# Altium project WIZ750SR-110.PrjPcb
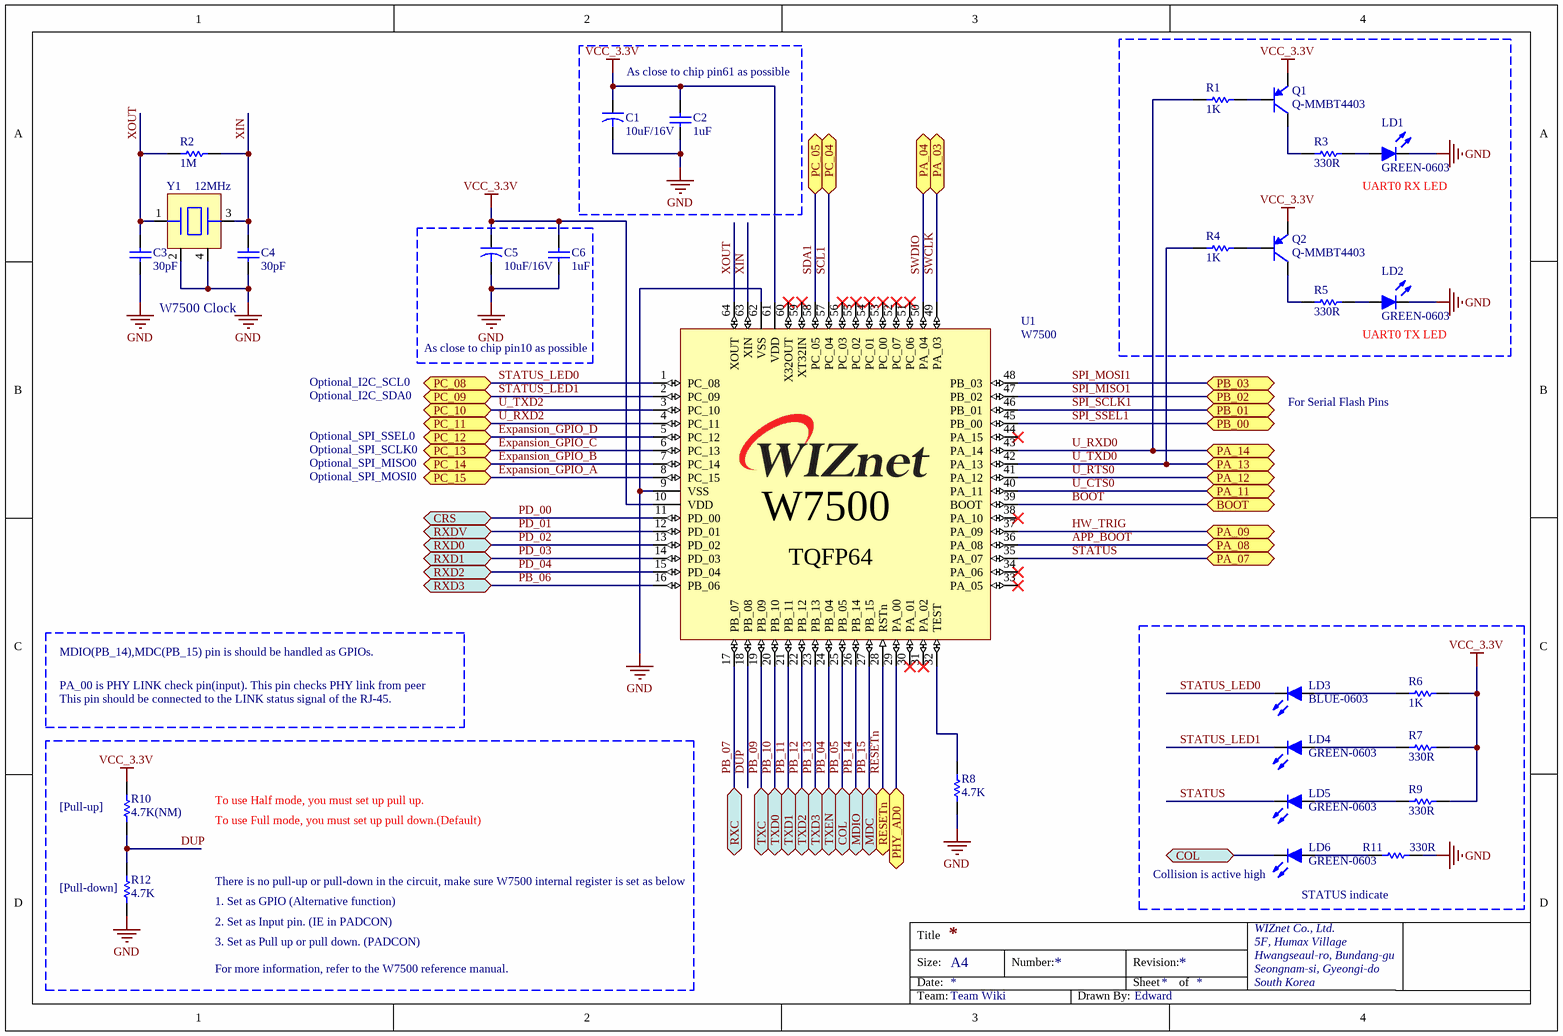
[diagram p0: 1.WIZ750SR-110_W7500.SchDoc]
4 sheets, 94 parts. Net scope: flat (ports and power ports of the same name join across sheets).
Board file: WIZ750SR-110.PcbDoc
Sheets:
  1.WIZ750SR-110_W7500.SchDoc
  2.WIZ750SR-110_IP101GRI.SchDoc
  3.WIZ750SR-110_OPTIONAL.SchDoc
  4.WIZ750SR-110_PINOUT.SchDoc

## Sheet 1.WIZ750SR-110_W7500.SchDoc
size A4; Team: Wiki

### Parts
C1  10uF/16V  [CAP-A Size]
C2  1uF  [CAP-0603]
C3  30pF  [CAP-0603]
C4  30pF  [CAP-0603]
C5  10uF/16V  [CAP-A Size]
C6  1uF  [CAP-0603]
LD1  GREEN-0603  [LED-0603-GREEN]
LD2  GREEN-0603  [LED-0603-GREEN]
LD3  BLUE-0603  [LED-0603-BLUE]
LD4  GREEN-0603  [LED-0603-GREEN]
LD5  GREEN-0603  [LED-0603-GREEN]
LD6  GREEN-0603  [LED-0603-GREEN]
Q1  Q-MMBT4403  [SOT-23-3L]
Q2  Q-MMBT4403  [SOT-23-3L]
R1  1K  [RES-0603]
R2  1M  [RES-0603]
R3  330R  [RES-0603]
R4  1K  [RES-0603]
R5  330R  [RES-0603]
R6  1K  [RES-0603]
R7  330R  [RES-0603]
R8  4.7K  [RES-0603]
R9  330R  [RES-0603]
R10  4.7K(NM)  [RES-0603]
R11  330R  [RES-0603]
R12  4.7K  [RES-0603]
U1  W7500  [W7500-LQFP64]
Y1  12MHz  [OSC-TZ1067B]

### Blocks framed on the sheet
As close to chip pin61 as possible: C1 C2
As close to chip pin10 as possible: C5 C6

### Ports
BOOT, COL, CRS, MDC, MDIO, PA_03, PA_04, PA_07, PA_08, PA_09, PA_11, PA_12, PA_13, PA_14, PB_00, PB_01, PB_02, PB_03, PC_04, PC_05, PC_08, PC_09, PC_10, PC_11, PC_12, PC_13, PC_14, PC_15, PHY_AD0, RESETn, RXC, RXD0, RXD1, RXD2, RXD3, RXDV, TXC, TXD0, TXD1, TXD2, TXD3, TXEN

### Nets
GND: C1.2 C2.1 C3.1 C4.1 C5.2 C6.1 LD1.2(K) LD2.2(K) R8.1 R11.2 R12.1 U1.9(VSS) U1.62(VSS) Y1.2 Y1.4
VCC_3.3V: C1.1 C2.2 C5.1 C6.2 Q1.2(E) Q2.2(E) R6.2 R7.2 R9.2 R10.2 U1.10(VDD) U1.61(VDD)
APP_BOOT: U1.36(PA_08) ; port PA_08
BOOT: U1.39(BOOT) ; port BOOT
DUP: R10.1 R12.2 U1.18(PB_08)
Expansion_GPIO_A: U1.8(PC_15) ; port PC_15
Expansion_GPIO_B: U1.7(PC_14) ; port PC_14
Expansion_GPIO_C: U1.6(PC_13) ; port PC_13
Expansion_GPIO_D: U1.5(PC_12) ; port PC_12
HW_TRIG: U1.37(PA_09) ; port PA_09
PB_04: U1.24(PB_04) ; port TXEN
PB_05: LD6.2(K) U1.25(PB_05) ; port COL
PB_06: U1.16(PB_06) ; port RXD3
PB_07: U1.17(PB_07) ; port RXC
PB_09: U1.19(PB_09) ; port TXC
PB_10: U1.20(PB_10) ; port TXD0
PB_11: U1.21(PB_11) ; port TXD1
PB_12: U1.22(PB_12) ; port TXD2
PB_13: U1.23(PB_13) ; port TXD3
PB_14: U1.26(PB_14) ; port MDIO
PB_15: U1.27(PB_15) ; port MDC
PD_00: U1.11(PD_00) ; port CRS
PD_01: U1.12(PD_01) ; port RXDV
PD_02: U1.13(PD_02) ; port RXD0
PD_03: U1.14(PD_03) ; port RXD1
PD_04: U1.15(PD_04) ; port RXD2
PHY_AD0: U1.29(PA_00) ; port PHY_AD0
RESETn: U1.28(RSTn) ; port RESETn
SCL1: U1.57(PC_04) ; port PC_04
SDA1: U1.58(PC_05) ; port PC_05
SPI_MISO1: U1.47(PB_02) ; port PB_02
SPI_MOSI1: U1.48(PB_03) ; port PB_03
SPI_SCLK1: U1.46(PB_01) ; port PB_01
SPI_SSEL1: U1.45(PB_00) ; port PB_00
STATUS: LD5.2(K) U1.35(PA_07) ; port PA_07
STATUS_LED0: LD3.2(K) U1.1(PC_08) ; port PC_08
STATUS_LED1: LD4.2(K) U1.2(PC_09) ; port PC_09
SWCLK: U1.49(PA_03) ; port PA_03
SWDIO: U1.50(PA_04) ; port PA_04
U_CTS0: U1.40(PA_11) ; port PA_11
U_RTS0: U1.41(PA_12) ; port PA_12
U_RXD0: R1.2 U1.43(PA_14) ; port PA_14
U_RXD2: U1.4(PC_11) ; port PC_11
U_TXD0: R4.2 U1.42(PA_13) ; port PA_13
U_TXD2: U1.3(PC_10) ; port PC_10
XIN: C4.2 R2.2 U1.63(XIN) Y1.3
XOUT: C3.2 R2.1 U1.64(XOUT) Y1.1
NetLD1_1: LD1.1(A) R3.1
NetLD2_1: LD2.1(A) R5.2
NetLD3_1: LD3.1(A) R6.1
NetLD4_1: LD4.1(A) R7.1
NetLD5_1: LD5.1(A) R9.1
NetLD6_1: LD6.1(A) R11.1
NetQ1_1: Q1.1(B) R1.1
NetQ1_3: Q1.3(C) R3.2
NetQ2_1: Q2.1(B) R4.1
NetQ2_3: Q2.3(C) R5.1
NetR8_2: R8.2 U1.32(TEST)

Not connected (* = marked no-connect by the designer): U1 30(PA_01)* 31(PA_02)* 33(PA_05)* 34(PA_06)* 38(PA_10)* 44(PA_15)* 51(PC_06)* 52(PC_07)* 53(PC_00)* 54(PC_01)* 55(PC_02)* 56(PC_03)* 59(XT32IN)* 60(X32OUT)*

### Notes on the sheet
- UART0 RX LED
- W7500 Clock
- Optional_I2C_SCL0
- UART0 TX LED
- Optional_I2C_SDA0
- Optional_SPI_SSEL0
- For Serial Flash Pins
- Optional_SPI_SCLK0
- Optional_SPI_MISO0
- Optional_SPI_MOSI0
- MDIO(PB_14),MDC(PB_15) pin is should be handled as GPIOs.
- PA_00 is PHY LINK check pin(input). This pin checks PHY link from peer
- This pin should be connected to the LINK status signal of the RJ-45.
- (near R10) [Pull-up]
- To use Half mode, you must set up pull up.
- To use Full mode, you must set up pull down.(Default)
- (near R12) [Pull-down]
- There is no pull-up or pull-down in the circuit, make sure W7500 internal register is set as below
- 1. Set as GPIO (Alternative function)
- 2. Set as Input pin. (IE in PADCON)
- (near LD6) Collision is active high
- STATUS indicate
- 3. Set as Pull up or pull down. (PADCON)
- For more information, refer to the W7500 reference manual.

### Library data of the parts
C1 C5 = CAP-A Size: Tantla CAP A Size EIA/IECQ 3216
C2-C4 C6 = CAP-0603: Ceramic CAP 0603(1608)
LD1-LD6 = LED-0603
Q1 Q2 = Q-MMBT4403: PNP General-Purpose Amplifier
R1-R12 = RES-0603
U1 = W7500: WIZnet ARM Cortex-M0
Y1 = OSC-TZ1067B-12MHz: X-tal 12MHz,3.2x2.5 SMD, CL=20pF

## Sheet 2.WIZ750SR-110_IP101GRI.SchDoc
size A4; Team: Wiki
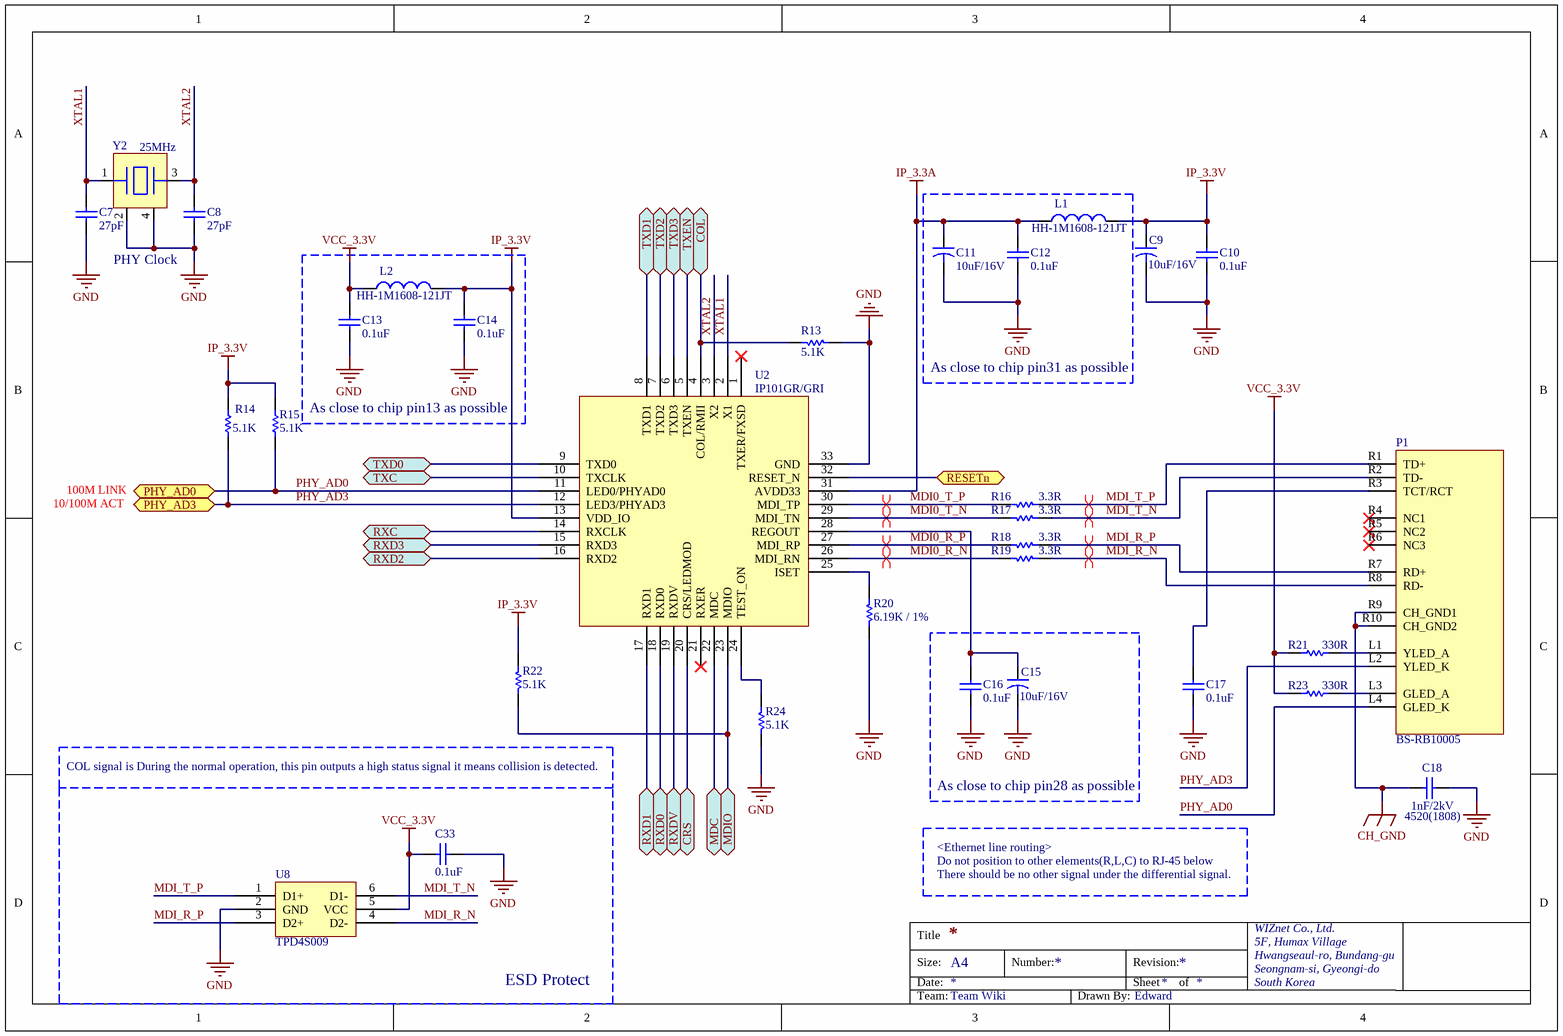
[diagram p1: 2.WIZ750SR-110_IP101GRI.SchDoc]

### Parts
C7  27pF  [CAP-0603]
C8  27pF  [CAP-0603]
C9  10uF/16V  [CAP-A Size]
C10  0.1uF  [CAP-0603]
C11  10uF/16V  [CAP-A Size]
C12  0.1uF  [CAP-0603]
C13  0.1uF  [CAP-0603]
C14  0.1uF  [CAP-0603]
C15  10uF/16V  [CAP-A Size]
C16  0.1uF  [CAP-0603]
C17  0.1uF  [CAP-0603]
C18  1nF/2kV  [CAP-1808]
C33  0.1uF  [CAP-0603]
L1  HH-1M1608-121JT  [IND-0603]
L2  HH-1M1608-121JT  [IND-0603]
P1  BS-RB10005  [RJ45-RB10005]
R13  5.1K  [RES-0603]
R14  5.1K  [RES-0603]
R15  5.1K  [RES-0603]
R16  3.3R  [RES-0603]
R17  3.3R  [RES-0603]
R18  3.3R  [RES-0603]
R19  3.3R  [RES-0603]
R20  6.19K / 1%  [RES-0603]
R21  330R  [RES-0603]
R22  5.1K  [RES-0603]
R23  330R  [RES-0603]
R24  5.1K  [RES-0603]
U2  IP101GR/GRI  [QFN32(0.4/4X4)]
U8  TPD4S009  [SOT-23-6L]
Y2  25MHz  [OSC-82J0626]

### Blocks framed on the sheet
As close to chip pin31 as possible: C11 C12 L1
As close to chip pin13 as possible: C13 C14 L2
As close to chip pin28 as possible: C15 C16

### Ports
COL, CRS, MDC, MDIO, PHY_AD0, PHY_AD3, RESETn, RXC, RXD0, RXD1, RXD2, RXD3, RXDV, TXC, TXD0, TXD1, TXD2, TXD3, TXEN

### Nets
CH_GND: C18.2 P1.R9(CH_GND1) P1.R10(CH_GND2)
GND: C7.1 C8.1 C9.2 C10.1 C11.2 C12.1 C13.1 C14.2 C15.2 C16.1 C17.1 C18.1 C33.2 R13.1 R20.1 R24.1 U2.33(GND) U8.2(GND) Y2.2 Y2.4
IP_3.3A: C11.1 C12.2 L1.1 U2.31(AVDD33)
IP_3.3V: C9.1 C10.2 C14.1 L1.2 L2.2 R14.1 R15.1 R22.2 U2.13(VDD_IO)
VCC_3.3V: C13.2 C33.1 L2.1 R21.1 R23.1 U8.5(VCC)
MDI0_R_N: R19.2 U2.26(MDI_RN)
MDI0_R_P: R18.2 U2.27(MDI_RP)
MDI0_T_N: R17.2 U2.29(MDI_TN)
MDI0_T_P: R16.2 U2.30(MDI_TP)
MDI_R_N: P1.R8(RD-) R19.1 U8.4(D2-)
MDI_R_P: P1.R7(RD+) R18.1 U8.3(D2+)
MDI_T_N: P1.R2(TD-) R17.1 U8.6(D1-)
MDI_T_P: P1.R1(TD+) R16.1 U8.1(D1+)
PB_04: U2.5(TXEN) ; port TXEN
PB_05: R13.2 U2.4(COL/RMII) ; port COL
PB_06: U2.15(RXD3) ; port RXD3
PB_07: U2.14(RXCLK) ; port RXC
PB_09: U2.10(TXCLK) ; port TXC
PB_10: U2.9(TXD0) ; port TXD0
PB_11: U2.8(TXD1) ; port TXD1
PB_12: U2.7(TXD2) ; port TXD2
PB_13: U2.6(TXD3) ; port TXD3
PB_14: R22.1 U2.23(MDIO) ; port MDIO
PB_15: U2.22(MDC) ; port MDC
PD_00: U2.20(CRS/LEDMOD) ; port CRS
PD_01: U2.19(RXDV) ; port RXDV
PD_02: U2.18(RXD0) ; port RXD0
PD_03: U2.17(RXD1) ; port RXD1
PD_04: U2.16(RXD2) ; port RXD2
PHY_AD0: P1.L4(GLED_K) R15.2 U2.11(LED0/PHYAD0) ; port PHY_AD0
PHY_AD3: P1.L2(YLED_K) R14.2 U2.12(LED3/PHYAD3) ; port PHY_AD3
RESETn: U2.32(RESET_N) ; port RESETn
XTAL1: C7.2 U2.2(X1) Y2.1
XTAL2: C8.2 U2.3(X2) Y2.3
NetC15_1: C15.1 C16.2 U2.28(REGOUT)
NetC17_2: C17.2 P1.R3(TCT/RCT)
NetP1_L1: P1.L1(YLED_A) R21.2
NetP1_L3: P1.L3(GLED_A) R23.2
NetR20_2: R20.2 U2.25(ISET)
NetR24_2: R24.2 U2.24(TEST_ON)

Not connected (* = marked no-connect by the designer): P1 R4(NC1)* R5(NC2)* R6(NC3)*; U2 1(TXER/FXSD)* 21(RXER)*

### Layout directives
differential pair: MDI0_R_N, MDI0_R_P, MDI0_T_N, MDI0_T_P, MDI_R_N, MDI_R_P, MDI_T_N, MDI_T_P

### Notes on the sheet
- PHY Clock
- 10/100M ACT
- 100M LINK
- (near R24) COL signal is During the normal operation, this pin outputs a high status signal it means collision is detected.
- <Ethernet line routing>
- (near C18) 4520(1808)
- Do not position to other elements(R,L,C) to RJ-45 below
- There should be no other signal under the differential signal.
- ESD Protect

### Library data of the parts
C7 C8 C10 C12-C14 C16 C17 C33 = CAP-0603: Ceramic CAP 0603(1608)
C9 C11 C15 = CAP-A Size: Tantla CAP A Size EIA/IECQ 3216
C18 = CAP-1808: Ceramic CAP 1808(4520)
L1 L2 = IND-0603: Inductor 0603(1608)
P1 = RB1-125BAG1A: 10/100 BASE-TX MAGJACK
R13-R24 = RES-0603
U2 = IP101GR/GRI: Pakage: VQFN-32
U8 = tpd4s009: 6-PIN SOT DBVor DCK Package
Y2 = OSC-82J0626-25MHz: X-tal 25MHz,3.2x2.5 SMD, CL=18pF

## Sheet 3.WIZ750SR-110_OPTIONAL.SchDoc
size A4; Team: Wiki
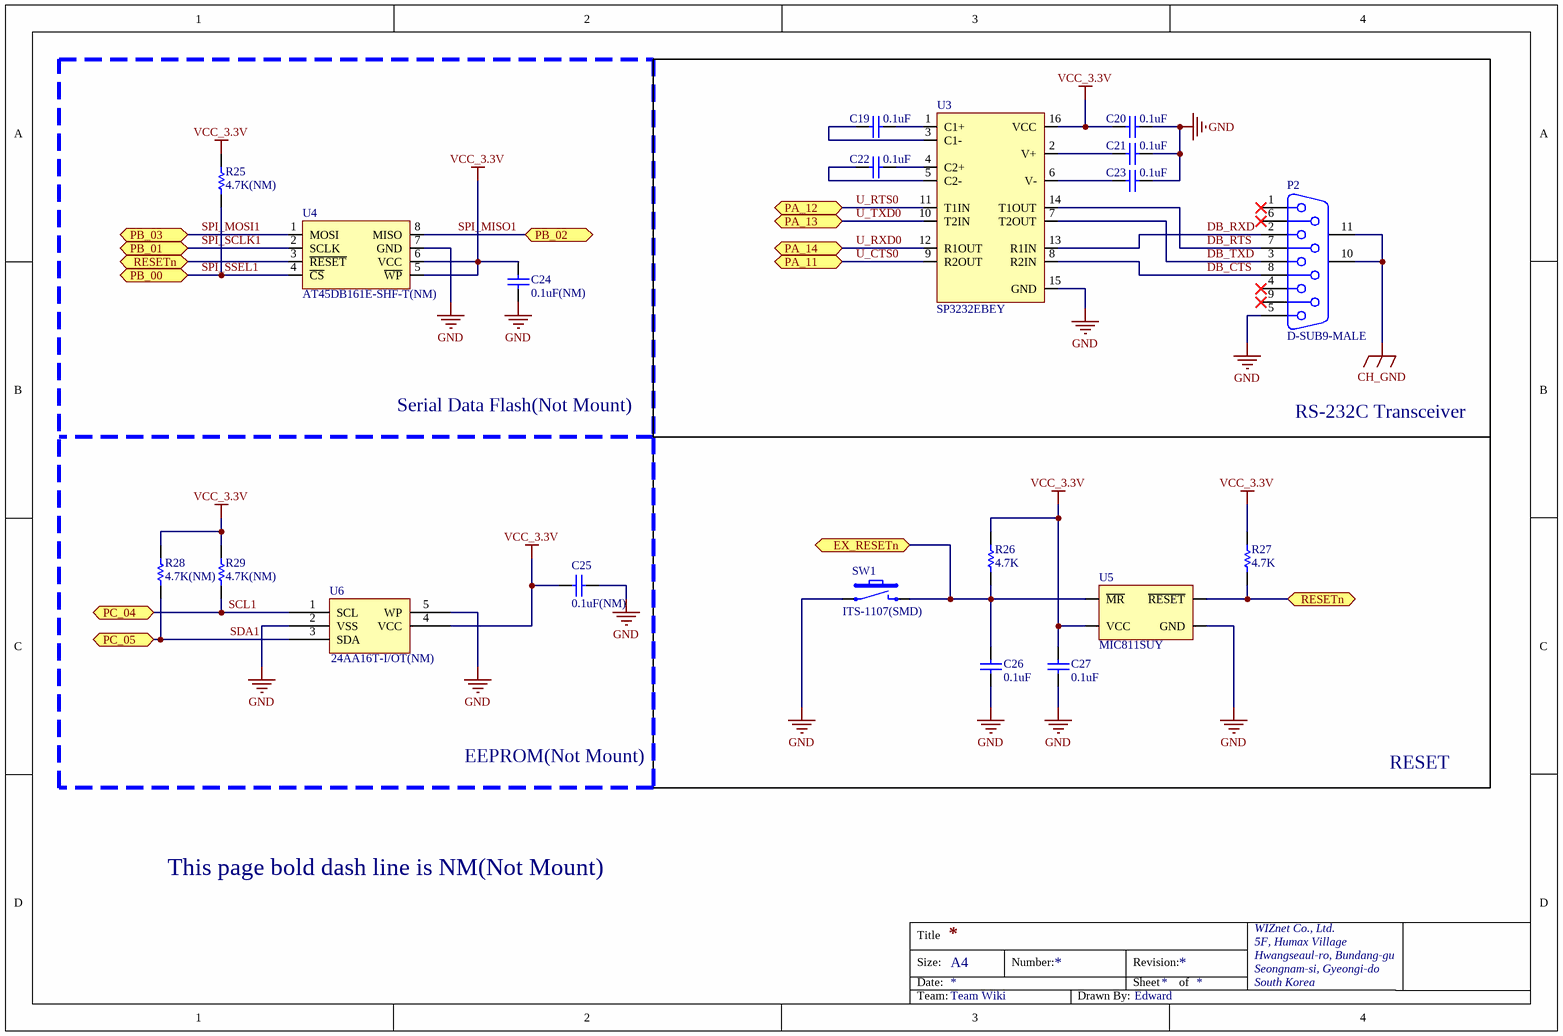
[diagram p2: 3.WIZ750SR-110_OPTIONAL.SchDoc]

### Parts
C19  0.1uF  [CAP-0603]
C20  0.1uF  [CAP-0603]
C21  0.1uF  [CAP-0603]
C22  0.1uF  [CAP-0603]
C23  0.1uF  [CAP-0603]
C24  0.1uF(NM)  [CAP-0603]
C25  0.1uF(NM)  [CAP-0603]
C26  0.1uF  [CAP-0603]
C27  0.1uF  [CAP-0603]
P2  D-SUB9-MALE  [D-SUB9-MALE]
R25  4.7K(NM)  [RES-0603]
R26  4.7K  [RES-0603]
R27  4.7K  [RES-0603]
R28  4.7K(NM)  [RES-0603]
R29  4.7K(NM)  [RES-0603]
SW1  ITS-1107(SMD)  [IT-1107(SMD)]
U3  SP3232EBEY  [TSSOP16(0.65/6.4)]
U4  AT45DB161E-SHF-T(NM)  [SO-08-EIAJ]
U5  MIC811SUY  [SOT-143]
U6  24AA16T-I/OT(NM)  [SOT-23-5L]

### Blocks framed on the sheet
RS-232C Transceiver: C19-C23 P2 U3

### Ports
EX_RESETn, PA_11, PA_12, PA_13, PA_14, PB_00, PB_01, PB_02, PB_03, PC_04, PC_05, RESETn

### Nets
CH_GND: P2.10(MH1) P2.11(MH2)
GND: C20.1 C21.1 C23.1 C24.2 C25.1 C26.1 C27.1 P2.5 SW1.1 U3.15(GND) U4.7(GND) U5.1(GND) U6.2(VSS) U6.5(WP)
VCC_3.3V: C20.2 C24.1 C25.2 C27.2 R25.2 R26.2 R27.2 R28.2 R29.2 U3.16(VCC) U4.5(~{WP}) U4.6(VCC) U5.4(VCC) U6.4(VCC)
DB_CTS: P2.8 U3.8(R2IN)
DB_RTS: P2.7 U3.14(T1OUT)
DB_RXD: P2.2 U3.13(R1IN)
DB_TXD: P2.3 U3.7(T2OUT)
EX_RESETn: C26.2 R26.1 SW1.2 U5.3(~{MR}) ; port EX_RESETn
RESETn: R27.1 U4.3(~{RESET}) U5.2(~{RESET}) ; port RESETn
SCL1: R29.1 U6.1(SCL) ; port PC_04
SDA1: R28.1 U6.3(SDA) ; port PC_05
SPI_MISO1: U4.8(MISO) ; port PB_02
SPI_MOSI1: U4.1(MOSI) ; port PB_03
SPI_SCLK1: U4.2(SCLK) ; port PB_01
SPI_SSEL1: R25.1 U4.4(~{CS}) ; port PB_00
U_CTS0: U3.9(R2OUT) ; port PA_11
U_RTS0: U3.11(T1IN) ; port PA_12
U_RXD0: U3.12(R1OUT) ; port PA_14
U_TXD0: U3.10(T2IN) ; port PA_13
NetC19_1: C19.1 U3.1(C1+)
NetC19_2: C19.2 U3.3(C1-)
NetC21_2: C21.2 U3.2(V+)
NetC22_1: C22.1 U3.4(C2+)
NetC22_2: C22.2 U3.5(C2-)
NetC23_2: C23.2 U3.6(V-)

Not connected (* = marked no-connect by the designer): P2 1* 4* 6* 9*

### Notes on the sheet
- Serial Data Flash(Not Mount)
- EEPROM(Not Mount)
- RESET
- This page bold dash line is NM(Not Mount)

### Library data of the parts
C19-C27 = CAP-0603: Ceramic CAP 0603(1608)
P2 = D-SUB9-MALE: D-SUB-9, MALE,  Right Angle; PackageDocument: O; Positions: 9; Gender: Receptacle
R25-R29 = RES-0603
SW1 = ITS-1107(SMD): TACT SW, SMD
U3 = SP3232EBEY: True +3.0V to +5.5V RS-232 Transceivers TSSOP16
U4 = AT45DB161E-SHF-T: 16-Mbit DataFlash, 2.3V or 2.5V Minimum SPI Serial Flash Memory
U5 = MIC811SUY: Microprocessor Reset Circuits
U6 = 24AAxxT-i-OT: SOT-23

## Sheet 4.WIZ750SR-110_PINOUT.SchDoc
size A4; Team: Wiki
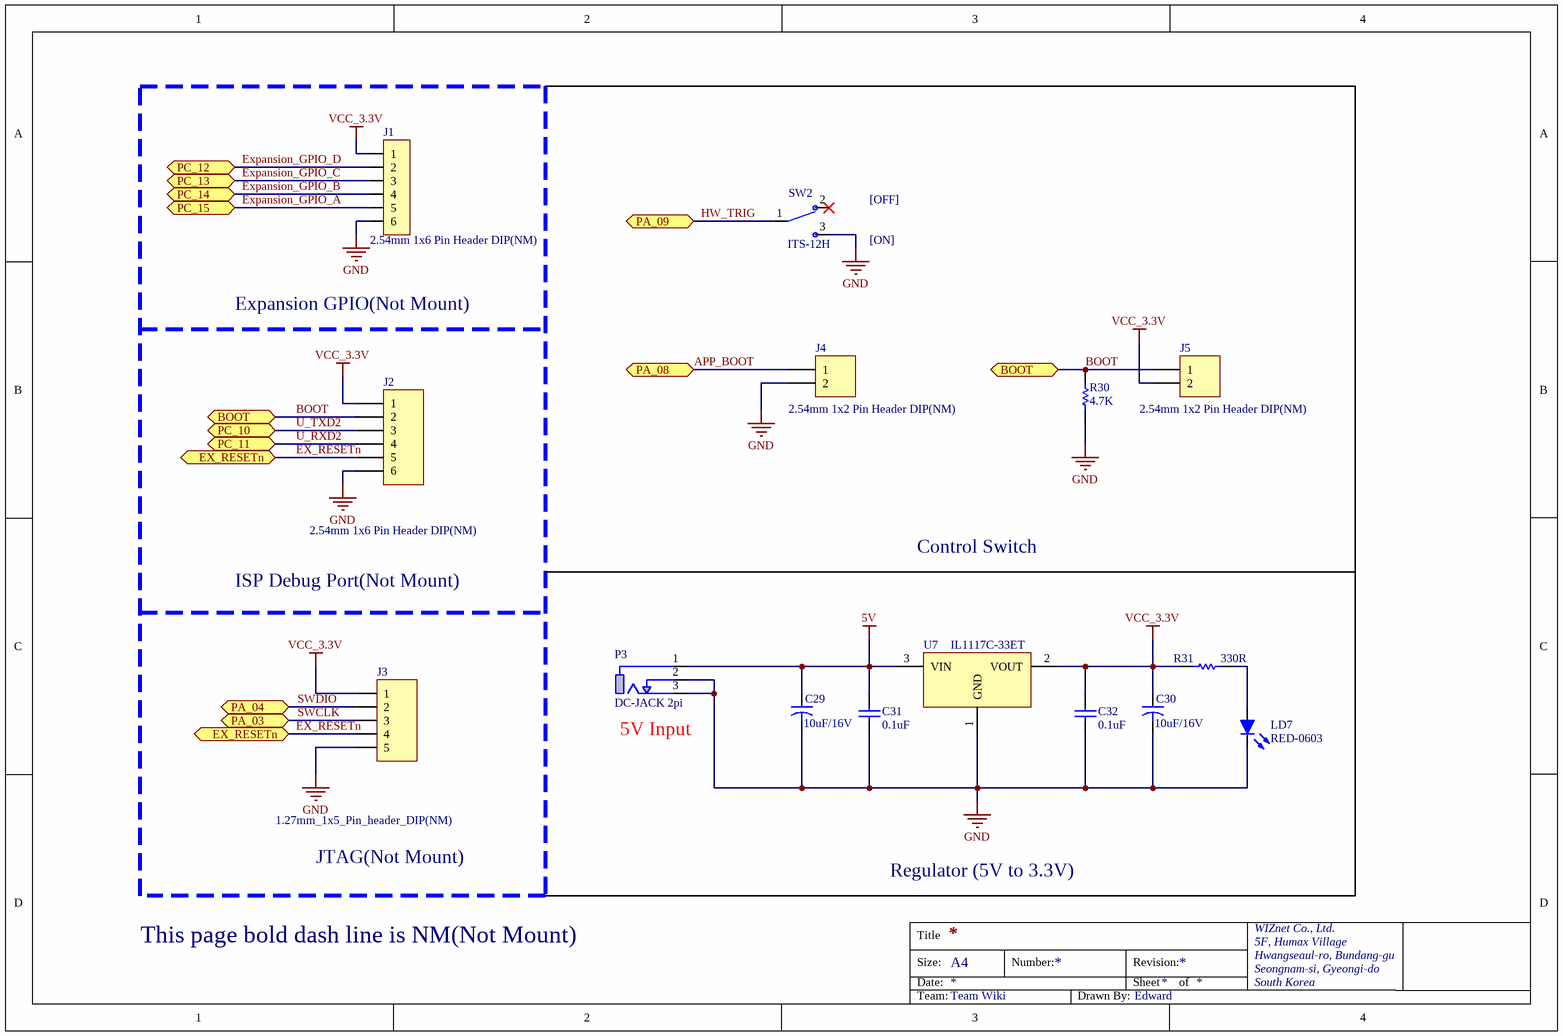
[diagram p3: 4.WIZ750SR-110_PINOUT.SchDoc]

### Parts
C29  10uF/16V  [CAP-A Size]
C30  10uF/16V  [CAP-A Size]
C31  0.1uF  [CAP-0603]
C32  0.1uF  [CAP-0603]
J1  2.54mm 1x6 Pin Header DIP(NM)  [IDC-1X6]
J2  2.54mm 1x6 Pin Header DIP(NM)  [IDC-1X6]
J3  1.27mm_1x5_Pin_header_DIP(NM)  [IDC-1X5(1.27MM)]
J4  2.54mm 1x2 Pin Header DIP(NM)  [IDC-1X2]
J5  2.54mm 1x2 Pin Header DIP(NM)  [IDC-1X2]
LD7  RED-0603  [LED-0603-RED]
P3  DC-JACK 2pi  [DC-JACK 2pi]
R30  4.7K  [RES-0603]
R31  330R  [RES-0603]
SW2  ITS-12H  [ITS-12H]
U7  IL1117C-33ET  [SOT-223]

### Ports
BOOT, EX_RESETn, PA_03, PA_04, PA_08, PA_09, PC_10, PC_11, PC_12, PC_13, PC_14, PC_15

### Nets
5V: C29.1 C31.2 P3.1(VCC) U7.3(VIN)
GND: C29.2 C30.2 C31.1 C32.1 J1.6 J2.6 J3.5 J4.2 LD7.2(K) P3.2(GND) P3.3(GND) R30.2 SW2.3 U7.1(GND)
VCC_3.3V: C30.1 C32.2 J1.1 J2.1 J3.1 J5.2 R31.1 U7.2(VOUT)
APP_BOOT: J4.1 ; port PA_08
BOOT: J2.2 J5.1 R30.1 ; port BOOT
EX_RESETn: J2.5 J3.4 ; port EX_RESETn
Expansion_GPIO_A: J1.5 ; port PC_15
Expansion_GPIO_B: J1.4 ; port PC_14
Expansion_GPIO_C: J1.3 ; port PC_13
Expansion_GPIO_D: J1.2 ; port PC_12
HW_TRIG: SW2.1 ; port PA_09
SWCLK: J3.3 ; port PA_03
SWDIO: J3.2 ; port PA_04
U_RXD2: J2.4 ; port PC_11
U_TXD2: J2.3 ; port PC_10
NetLD7_1: LD7.1(A) R31.2

Not connected (* = marked no-connect by the designer): SW2 2*

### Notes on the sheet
- [ON]
- [OFF]
- Expansion GPIO(Not Mount)
- Control Switch
- ISP Debug Port(Not Mount)
- (near P3) 5V Input
- JTAG(Not Mount)
- Regulator (5V to 3.3V)
- This page bold dash line is NM(Not Mount)

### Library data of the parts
C29 C30 = CAP-A Size: Tantla CAP A Size EIA/IECQ 3216
C31 C32 = CAP-0603: Ceramic CAP 0603(1608)
J1 = 2.54mm 1x6 Pin Header DIP
J2 = Header 6: Header, 6-Pin
J3 = 1.27mm_1x5_Pin_header_DIP
J4 J5 = Header 1x2: pin header 2.54mm 1x2
LD7 = LED-0603
R30 R31 = RES-0603
SW2 = ITS-12H: Slide Switch
U7 = IL1117C-33ET: 1A, 3.3V

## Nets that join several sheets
CH_GND: 2.WIZ750SR-110_IP101GRI (C18.2 P1.R9 P1.R10), 3.WIZ750SR-110_OPTIONAL (P2.10 P2.11)
GND: 1.WIZ750SR-110_W7500 (15 pins), 2.WIZ750SR-110_IP101GRI (20 pins), 3.WIZ750SR-110_OPTIONAL (14 pins), 4.WIZ750SR-110_PINOUT (14 pins)
VCC_3.3V: 1.WIZ750SR-110_W7500 (12 pins), 2.WIZ750SR-110_IP101GRI (6 pins), 3.WIZ750SR-110_OPTIONAL (14 pins), 4.WIZ750SR-110_PINOUT (8 pins)
APP_BOOT: 1.WIZ750SR-110_W7500 (U1.36), 4.WIZ750SR-110_PINOUT (J4.1)
BOOT: 1.WIZ750SR-110_W7500 (U1.39), 4.WIZ750SR-110_PINOUT (J2.2 J5.1 R30.1)
EX_RESETn: 3.WIZ750SR-110_OPTIONAL (C26.2 R26.1 SW1.2 U5.3), 4.WIZ750SR-110_PINOUT (J2.5 J3.4)
Expansion_GPIO_A: 1.WIZ750SR-110_W7500 (U1.8), 4.WIZ750SR-110_PINOUT (J1.5)
Expansion_GPIO_B: 1.WIZ750SR-110_W7500 (U1.7), 4.WIZ750SR-110_PINOUT (J1.4)
Expansion_GPIO_C: 1.WIZ750SR-110_W7500 (U1.6), 4.WIZ750SR-110_PINOUT (J1.3)
Expansion_GPIO_D: 1.WIZ750SR-110_W7500 (U1.5), 4.WIZ750SR-110_PINOUT (J1.2)
HW_TRIG: 1.WIZ750SR-110_W7500 (U1.37), 4.WIZ750SR-110_PINOUT (SW2.1)
PB_04: 1.WIZ750SR-110_W7500 (U1.24), 2.WIZ750SR-110_IP101GRI (U2.5)
PB_05: 1.WIZ750SR-110_W7500 (LD6.2 U1.25), 2.WIZ750SR-110_IP101GRI (R13.2 U2.4)
PB_06: 1.WIZ750SR-110_W7500 (U1.16), 2.WIZ750SR-110_IP101GRI (U2.15)
PB_07: 1.WIZ750SR-110_W7500 (U1.17), 2.WIZ750SR-110_IP101GRI (U2.14)
PB_09: 1.WIZ750SR-110_W7500 (U1.19), 2.WIZ750SR-110_IP101GRI (U2.10)
PB_10: 1.WIZ750SR-110_W7500 (U1.20), 2.WIZ750SR-110_IP101GRI (U2.9)
PB_11: 1.WIZ750SR-110_W7500 (U1.21), 2.WIZ750SR-110_IP101GRI (U2.8)
PB_12: 1.WIZ750SR-110_W7500 (U1.22), 2.WIZ750SR-110_IP101GRI (U2.7)
PB_13: 1.WIZ750SR-110_W7500 (U1.23), 2.WIZ750SR-110_IP101GRI (U2.6)
PB_14: 1.WIZ750SR-110_W7500 (U1.26), 2.WIZ750SR-110_IP101GRI (R22.1 U2.23)
PB_15: 1.WIZ750SR-110_W7500 (U1.27), 2.WIZ750SR-110_IP101GRI (U2.22)
PD_00: 1.WIZ750SR-110_W7500 (U1.11), 2.WIZ750SR-110_IP101GRI (U2.20)
PD_01: 1.WIZ750SR-110_W7500 (U1.12), 2.WIZ750SR-110_IP101GRI (U2.19)
PD_02: 1.WIZ750SR-110_W7500 (U1.13), 2.WIZ750SR-110_IP101GRI (U2.18)
PD_03: 1.WIZ750SR-110_W7500 (U1.14), 2.WIZ750SR-110_IP101GRI (U2.17)
PD_04: 1.WIZ750SR-110_W7500 (U1.15), 2.WIZ750SR-110_IP101GRI (U2.16)
PHY_AD0: 1.WIZ750SR-110_W7500 (U1.29), 2.WIZ750SR-110_IP101GRI (P1.L4 R15.2 U2.11)
RESETn: 1.WIZ750SR-110_W7500 (U1.28), 2.WIZ750SR-110_IP101GRI (U2.32), 3.WIZ750SR-110_OPTIONAL (R27.1 U4.3 U5.2)
SCL1: 1.WIZ750SR-110_W7500 (U1.57), 3.WIZ750SR-110_OPTIONAL (R29.1 U6.1)
SDA1: 1.WIZ750SR-110_W7500 (U1.58), 3.WIZ750SR-110_OPTIONAL (R28.1 U6.3)
SPI_MISO1: 1.WIZ750SR-110_W7500 (U1.47), 3.WIZ750SR-110_OPTIONAL (U4.8)
SPI_MOSI1: 1.WIZ750SR-110_W7500 (U1.48), 3.WIZ750SR-110_OPTIONAL (U4.1)
SPI_SCLK1: 1.WIZ750SR-110_W7500 (U1.46), 3.WIZ750SR-110_OPTIONAL (U4.2)
SPI_SSEL1: 1.WIZ750SR-110_W7500 (U1.45), 3.WIZ750SR-110_OPTIONAL (R25.1 U4.4)
SWCLK: 1.WIZ750SR-110_W7500 (U1.49), 4.WIZ750SR-110_PINOUT (J3.3)
SWDIO: 1.WIZ750SR-110_W7500 (U1.50), 4.WIZ750SR-110_PINOUT (J3.2)
U_CTS0: 1.WIZ750SR-110_W7500 (U1.40), 3.WIZ750SR-110_OPTIONAL (U3.9)
U_RTS0: 1.WIZ750SR-110_W7500 (U1.41), 3.WIZ750SR-110_OPTIONAL (U3.11)
U_RXD0: 1.WIZ750SR-110_W7500 (R1.2 U1.43), 3.WIZ750SR-110_OPTIONAL (U3.12)
U_RXD2: 1.WIZ750SR-110_W7500 (U1.4), 4.WIZ750SR-110_PINOUT (J2.4)
U_TXD0: 1.WIZ750SR-110_W7500 (R4.2 U1.42), 3.WIZ750SR-110_OPTIONAL (U3.10)
U_TXD2: 1.WIZ750SR-110_W7500 (U1.3), 4.WIZ750SR-110_PINOUT (J2.3)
